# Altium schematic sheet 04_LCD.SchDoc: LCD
size A3; Date: 3/31/2015; Author: P.A.; CompanyName: STMicroelectronics; Organization: Microcontrollers Division; Address1: 12, Rue Jules HOROWITZ; Address2: 38019 Grenoble; Address3: FRANCE; DocumentNumber: 7; Revision: E-01; SheetNumber: 7; SheetTotal: 12; Project: STM32F413H-DISCO
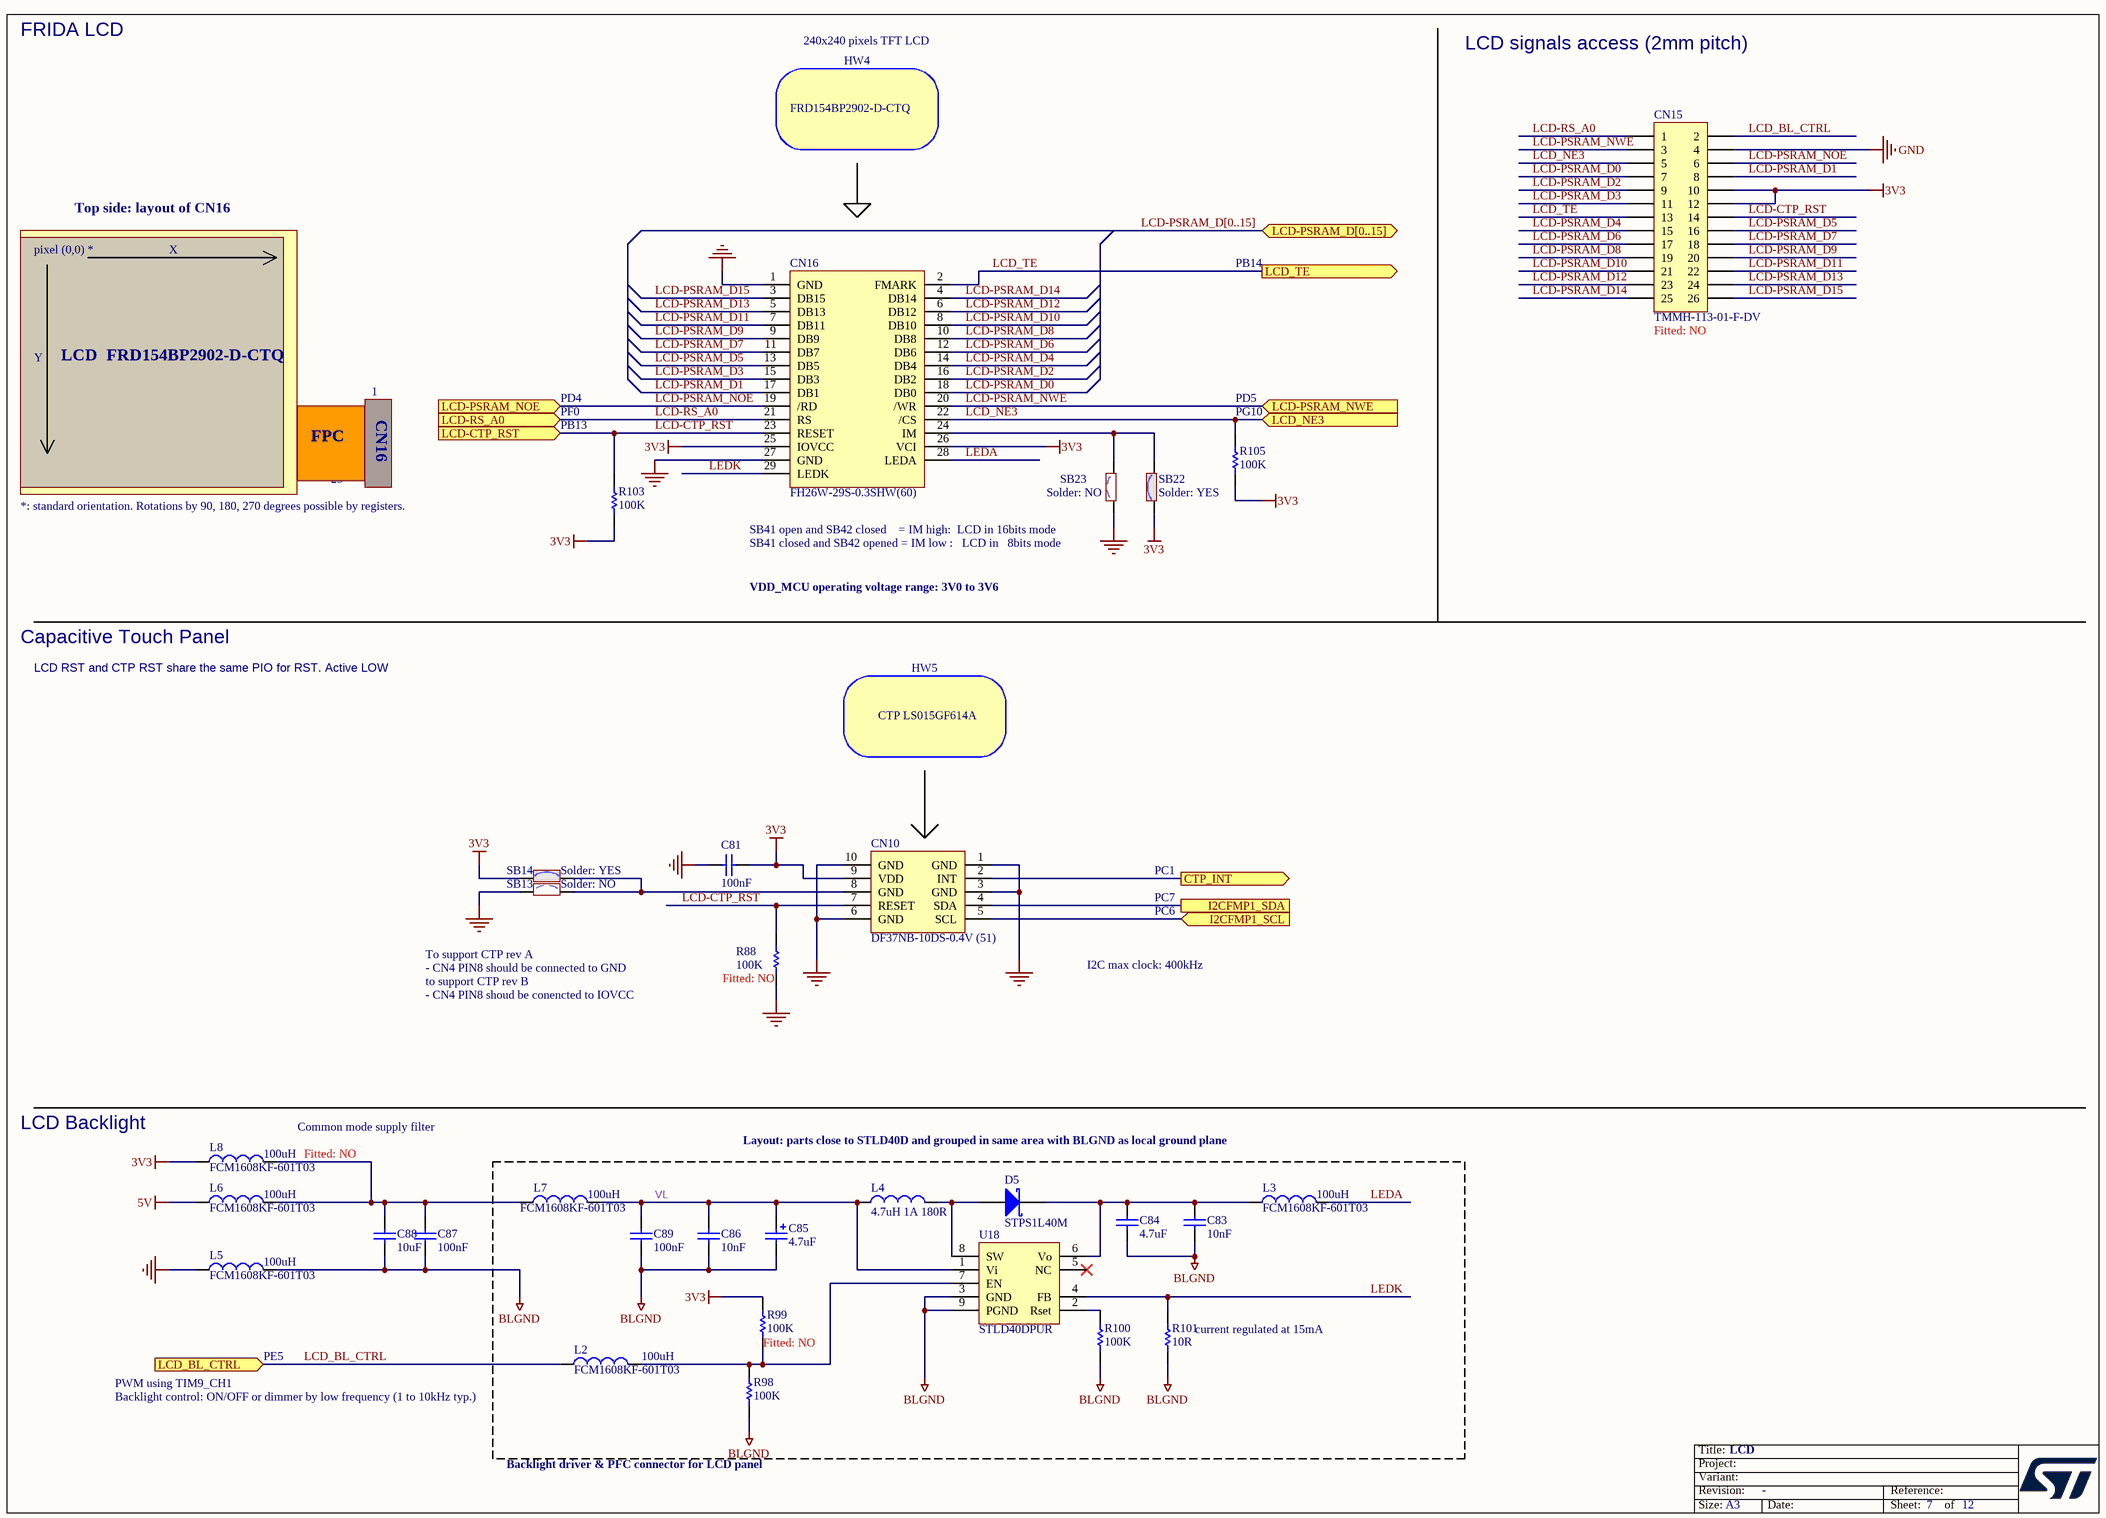
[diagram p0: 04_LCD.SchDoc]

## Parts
C81  100nF  [C0402]
C83  10nF  [C0402]
C84  4.7uF  [C1206]
C85  4.7uF  [CPOL_TAJ-A_1206_H180]
C86  10nF  [C0402]
C87  100nF  [C0402]
C88  10uF  [C0805]
C89  100nF  [C0402]
CN10  DF37NB-10DS-0.4V (51)  [CON_HRS_DF37NB-10DS-04V]
CN15  TMMH-113-01-F-DV  Fitted: NO  [CON_SAMTEC_TMMH-113-01-F-DV]
CN16  FH26W-29S-0.3SHW(60)  [CON_HRS_FH26-29S-03SHW]
D5  STPS1L40M  [DIO_DO216-AA]
HW4  FRD154BP2902-D-CTQ  (mechanical)
HW5  CTP LS015GF614A  [LCD_DRAWING_PROJET-MB1274]  (mechanical)
L2  100uH  Manuf_Part_1: FCM1608KF-601T03  [L0603]
L3  100uH  Manuf_Part_1: FCM1608KF-601T03  [L0603]
L4  4.7uH 1A 180R  [L1210_LQH]
L5  100uH  Manuf_Part_1: FCM1608KF-601T03  [L0603]
L6  100uH  Manuf_Part_1: FCM1608KF-601T03  [L0603]
L7  100uH  Manuf_Part_1: FCM1608KF-601T03  [L0603]
L8  100uH  Manuf_Part_1: FCM1608KF-601T03  Fitted: NO  [L0603]
R88  100K  Fitted: NO  [R0402]
R98  100K  [R0402]
R99  100K  Fitted: NO  [R0402]
R100  100K  [R0402]
R101  10R  [R0603]
R103  100K  [R0402]
R105  100K  [R0402]
SB13  Solder: NO  [SOLDER-BRIDGE_R0603-0R]  (hidden comment: SB_OFF)
SB14  Solder: YES  [SOLDER-BRIDGE_R0603-0R]  (hidden comment: SB_ON)
SB22  Solder: YES  [SOLDER-BRIDGE_R0603-0R]  (hidden comment: SB_ON)
SB23  Solder: NO  [SOLDER-BRIDGE_R0603-0R]  (hidden comment: SB_OFF)
U18  STLD40DPUR  [ICC_QFN8-EPAD_3X3_P065]

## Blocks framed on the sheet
current regulated at 15mA: C83-C86 C89 D5 L2-L4 L7 R98-R101 U18

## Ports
CTP_INT (out), I2CFMP1_SCL (in), I2CFMP1_SDA, LCD-CTP_RST (in), LCD-PSRAM_D[0..15] (bidir), LCD-PSRAM_NOE (in), LCD-PSRAM_NWE (in), LCD-RS_A0 (in), LCD_BL_CTRL (in), LCD_NE3 (in), LCD_TE (out)

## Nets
3V3: C81.1 CN10.9(VDD) CN15.10 CN15.12 CN16.25(IOVCC) CN16.26(VCI) L8.1 R99.2 R103.1 R105.1 SB14.1 SB22.1
5V: L6.1
BLGND: C83.1 C84.1 C85.2 C86.1 C87.1 C88.1 C89.1 L5.2 R98.1 R100.1 R101.1 U18.3(GND) U18.9(PGND)
GND: C81.2 CN10.1(GND) CN10.3(GND) CN10.6(GND) CN10.10(GND) CN15.4 CN16.1(GND) CN16.27(GND) L5.1 R88.1 SB13.1 SB23.1
CTP_INT: CN10.2(INT) ; port CTP_INT
I2CFMP1_SCL: CN10.5(SCL) ; port I2CFMP1_SCL
I2CFMP1_SDA: CN10.4(SDA) ; port I2CFMP1_SDA
LCD-CTP_RST: CN10.7(RESET) CN15.14 CN16.23(RESET) R88.2 R103.2 ; port LCD-CTP_RST
LCD-PSRAM_D0: CN15.7 CN16.18(DB0)
LCD-PSRAM_D1: CN15.8 CN16.17(DB1)
LCD-PSRAM_D2: CN15.9 CN16.16(DB2)
LCD-PSRAM_D3: CN15.11 CN16.15(DB3)
LCD-PSRAM_D4: CN15.15 CN16.14(DB4)
LCD-PSRAM_D5: CN15.16 CN16.13(DB5)
LCD-PSRAM_D6: CN15.17 CN16.12(DB6)
LCD-PSRAM_D7: CN15.18 CN16.11(DB7)
LCD-PSRAM_D8: CN15.19 CN16.10(DB8)
LCD-PSRAM_D9: CN15.20 CN16.9(DB9)
LCD-PSRAM_D10: CN15.21 CN16.8(DB10)
LCD-PSRAM_D11: CN15.22 CN16.7(DB11)
LCD-PSRAM_D12: CN15.23 CN16.6(DB12)
LCD-PSRAM_D13: CN15.24 CN16.5(DB13)
LCD-PSRAM_D14: CN15.25 CN16.4(DB14)
LCD-PSRAM_D15: CN15.26 CN16.3(DB15)
LCD-PSRAM_NOE: CN15.6 CN16.19(/RD) ; port LCD-PSRAM_NOE
LCD-PSRAM_NWE: CN15.3 CN16.20(/WR) ; port LCD-PSRAM_NWE
LCD-RS_A0: CN15.1 CN16.21(RS) ; port LCD-RS_A0
LCD_BL_CTRL: CN15.2 L2.1 ; port LCD_BL_CTRL
LCD_NE3: CN15.5 CN16.22(/CS) R105.2 ; port LCD_NE3
LCD_TE: CN15.13 CN16.2(FMARK) ; port LCD_TE
LEDA: CN16.28(LEDA) L3.2
LEDK: CN16.29(LEDK) R101.2 U18.4(FB)
VL: C85.1 C86.2 C89.2 L4.1 L7.2 U18.1(Vi)
NetC83_2: C83.2 C84.2 D5.2(K) L3.1 U18.6(Vo)
NetC87_2: C87.2 C88.2 L6.2 L7.1 L8.2
NetCN10_8: CN10.8(GND) SB13.2 SB14.2
NetCN16_24: CN16.24(IM) SB22.2 SB23.2
NetD5_1: D5.1(A) L4.2 U18.8(SW)
NetL2_2: L2.2 R98.2 R99.1 U18.7(EN)
NetR100_2: R100.2 U18.2(Rset)

Not connected (* = marked no-connect by the designer): U18 5(NC)*

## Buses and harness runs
bus LCD-PSRAM_D[0..15] = port LCD-PSRAM_D[0..15]

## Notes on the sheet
- FRIDA LCD
- 240x240 pixels TFT LCD
- LCD signals access (2mm pitch)
- pixel (0,0) *
- Top side: layout of CN16
- X
- PB14
- Y
- LCD  FRD154BP2902-D-CTQ
- FPC
- 1
- CN16
- PD4
- PF0
- PB13
- (near R105) PD5
- (near R105) PG10
- *: standard orientation. Rotations by 90, 180, 270 degrees possible by registers.
- 29
- SB41 open and SB42 closed    = IM high:  LCD in 16bits mode
  SB41 closed and SB42 opened = IM low :   LCD in   8bits mode
- VDD_MCU operating voltage range: 3V0 to 3V6
- Capacitive Touch Panel
- LCD RST and CTP RST share the same PIO for RST. Active LOW
- PC1
- PC6
- PC7
- To support CTP rev A
  - CN4 PIN8 should be connected to GND
  to support CTP rev B
  - CN4 PIN8 shoud be conencted to IOVCC
- I2C max clock: 400kHz
- LCD Backlight
- (near L8) Common mode supply filter
- Layout: parts close to STLD40D and grouped in same area with BLGND as local ground plane
- (near L2) Backlight control: ON/OFF or dimmer by low frequency (1 to 10kHz typ.)
- PWM using TIM9_CH1
- PE5
- Backlight driver & PFC connector for LCD panel

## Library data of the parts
C81 C87 C89 = Cap_100nF_X7R_10%_0402: Capacitor,100nF,16V,X7R,10%,0402,YAGEO; Manuf_Part_1: CC0402KRX7R7BB104; Fitted: YES; Ordered_By: Subcon
C83 C86 = Cap_10nF_X7R_10%_0402: Capacitor,10nF,16V,X7R,10%,0402,YAGEO; Manuf_Part_1: CC0402KRX7R7BB103; Fitted: YES; Ordered_By: Subcon
C84 = Cap_4.7uF_X7R_10%_1206: Capacitor,4.7uF,50V, X7R,10%,1206,AVX; Manuf_Part_1: 12065C475KAT2A; Fitted: YES; Ordered_By: Subcon
C85 = Cap_4.7uF_POL_10%_TANA: Polarized Capacitor,4.7uF,16V,10%,typeA,AVX; Manuf_Part_1: TAJA475K016R; Fitted: YES; Ordered_By: Subcon
C88 = Cap_10uF_X5R_10%_0805: Capacitor,10uF,25V,X5R,10%,0805,YAGEO; Manuf_Part_1: CC0805KRX5R8BB106; Fitted: YES; Ordered_By: Subcon
CN10 = DF37NB-10DS-0.4V (5x): Header, 5-Pin, Dual row; Manuf_1: Hirose; Ordered_by: Subcon; Fitted: YES
CN15 = Header TMMH 13X2 2mm (.0787"): 26 Position Receptacle Connector 0.079" (2.00mm) Surface Mount; Manuf_1: SAMTEC; Ordered_By: Subcon
CN16 = FH26-29S-0.3SHW: 29pins FPC connector; Manuf_1: Hirose; Fitted: YES; Ordered_By: Subcon
D5 = STPS1L40M: Low Drop power Schottky rectifier(1A, 40V, 0.4V); Manuf_1: STM; Ref St: 9151085; ECCN_US/EU: EAR99/NEC; Fitted: YES
HW4 = BoM_Item: TFT LCD 240x240 pixels; Manuf_1: FRIDA; Ordered_By: Subcon; ECCN_US/EU: EAR99/NEC; Fitted: YES
HW5 = BoM_Item: Self-Capacitive touch Panel; Manuf_Part_1: FRIDA; Ordered_By: Subcon; ECCN_US/EU: EAR99/NEC; Comments: assembled on LCD; Fitted: YES
L2 L3 L5-L7 = BEAD_600R_350MA_0603: Bead,600R,350mA,0603; Manuf_2: TDK; Manuf_Part_2: MPZ1608S300A; Manuf_1: Tai-tech; Manuf_Part_3: BLM18PG121SN1D; Manuf_3: MURATA; Fitted: YES; Ordered_By: Subcon
L4 = Ind_4.7uH_1A_30%: FIXED IND 4.7UH 1A 180 MOHM 30% SMD; Manuf_Part_1: LQH32PN4R7NN0L; Manuf_1: MURATA; Fitted: YES; Order_Code: 490-5338-1-ND; Ordered_By: Subcon
L8 = BEAD_600R_350MA_0603: Bead,600R,350mA,0603; Manuf_2: TDK; Manuf_Part_2: MPZ1608S300A; Manuf_1: Tai-tech; Manuf_Part_3: BLM18PG121SN1D; Manuf_3: MURATA; Ordered_By: Subcon
R88 R99 = Res_100K_1%_0402: Resistor,100K,0402,1%,YAGEO; Manuf_Part_2: RT0402FRE07100KL; Manuf_Part_1: RC0402FR-07100KL; Ordered_By: Subcon
R98 R100 R103 R105 = Res_100K_1%_0402: Resistor,100K,0402,1%,YAGEO; Manuf_Part_2: RT0402FRE07100KL; Manuf_Part_1: RC0402FR-07100KL; Fitted: YES; Ordered_By: Subcon
R101 = Res_10_1%_0603: Resistor,10R,0603,1%,ROHM,1/4W; Manuf_Part_1: ESR03EZPF10R0; Fitted: YES; Ordered_By: Subcon
SB13 SB23 = SB_OFF: Solder Bridge OFF; Fitted: NO; Ordered_By: Subcon
SB14 SB22 = SB_ON: Solder Bridge ON; Ordered_by: Subcon
U18 = STLD40DPUR: White LED power supply for large display backlight, QFN8; Manuf_1: STM; ECCN_US/EU: EAR99/NEC; Fitted: YES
